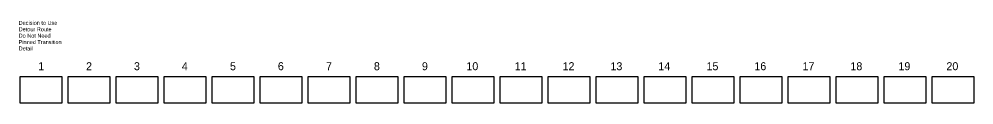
# Model space of a CAD drawing. Extents: x 10064 to 81668, y 7924 to 14128.
import ezdxf

# ---------------------------------------------------------------- set-up
doc = ezdxf.new("R2010")
doc.units = 0
doc.layers.add('dsnCellElements', color=7, linetype='Continuous')
doc.layers.add('SheetText', color=7, linetype='Continuous')

msp = doc.modelspace()

# ---------------------------------------------------------------- linework, layer by layer
at = {"layer": 'SheetText'}
for points in [[(10133, 9944), (13268, 9944), (13268, 7924), (10133, 7924)], [(13733, 9944), (16868, 9944), (16868, 7924), (13733, 7924)], [(17333, 9944), (20468, 9944), (20468, 7924), (17333, 7924)], [(20933, 9944), (24068, 9944), (24068, 7924), (20933, 7924)], [(24533, 9944), (27668, 9944), (27668, 7924), (24533, 7924)], [(28133, 9944), (31268, 9944), (31268, 7924), (28133, 7924)], [(31733, 9944), (34868, 9944), (34868, 7924), (31733, 7924)], [(35333, 9944), (38468, 9944), (38468, 7924), (35333, 7924)], [(38933, 9944), (42068, 9944), (42068, 7924), (38933, 7924)], [(42533, 9944), (45668, 9944), (45668, 7924), (42533, 7924)], [(46133, 9944), (49268, 9944), (49268, 7924), (46133, 7924)], [(49733, 9944), (52868, 9944), (52868, 7924), (49733, 7924)], [(53333, 9944), (56468, 9944), (56468, 7924), (53333, 7924)], [(56933, 9944), (60068, 9944), (60068, 7924), (56933, 7924)], [(60533, 9944), (63668, 9944), (63668, 7924), (60533, 7924)], [(64133, 9944), (67268, 9944), (67268, 7924), (64133, 7924)], [(67733, 9944), (70868, 9944), (70868, 7924), (67733, 7924)], [(71333, 9944), (74468, 9944), (74468, 7924), (71333, 7924)], [(74933, 9944), (78068, 9944), (78068, 7924), (74933, 7924)], [(78533, 9944), (81668, 9944), (81668, 7924), (78533, 7924)]]:
    msp.add_lwpolyline(points, close=True, dxfattribs=at)

# ---------------------------------------------------------------- texts
at = {"layer": 'dsnCellElements'}
for s, p in [('Decision to Use ', (10031, 13812)), ('Detour Route', (10031, 13332)), ('Do Not Need ', (10031, 12852)), ('Pinned Transition', (10031, 12372)), ('Detail', (10031, 11892))]:
    msp.add_text(s, height=300, dxfattribs=at).set_placement(p)
at = {"layer": 'SheetText'}
for s, p in [('1', (11497, 10409)), ('2', (15086, 10409)), ('3', (18678, 10409)), ('4', (22268, 10409)), ('5', (25881, 10409)), ('6', (29470, 10409)), ('7', (33080, 10409)), ('8', (36673, 10409)), ('9', (40273, 10409)), ('10', (43606, 10409)), ('11', (47230, 10409)), ('12', (50820, 10409)), ('13', (54411, 10409)), ('14', (58001, 10409)), ('15', (61614, 10409)), ('16', (65204, 10409)), ('17', (68814, 10409)), ('18', (72406, 10409)), ('19', (76007, 10409)), ('20', (79606, 10409))]:
    msp.add_text(s, height=600, dxfattribs=at).set_placement(p)

doc.saveas('drawing.dxf')
